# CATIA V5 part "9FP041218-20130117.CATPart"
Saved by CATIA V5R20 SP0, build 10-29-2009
Part number: 9FP041218-20130117
Revision: ANY
Definition: UNKNOWN
Nomenclature: 9FP041218-20130117
Source: Unknown
Bounding box of the stored display mesh (mm): x -9 to 9, y -9 to 9, z 0 to 8
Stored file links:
  C:\Users\Utente\Desktop\IO LAVORO\3D X SITO CF\CUMSA\3D files PF\PF 124200\9FP041218-20130117.CATPart
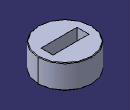
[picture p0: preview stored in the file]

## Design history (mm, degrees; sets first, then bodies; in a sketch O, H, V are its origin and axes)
Body1 "Chaflán1" (main body)
  Solid1: solid without history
